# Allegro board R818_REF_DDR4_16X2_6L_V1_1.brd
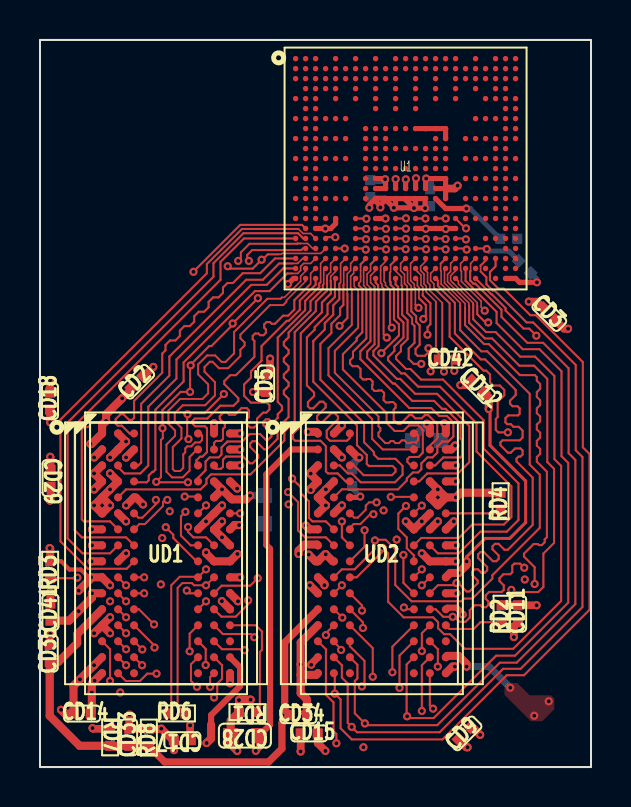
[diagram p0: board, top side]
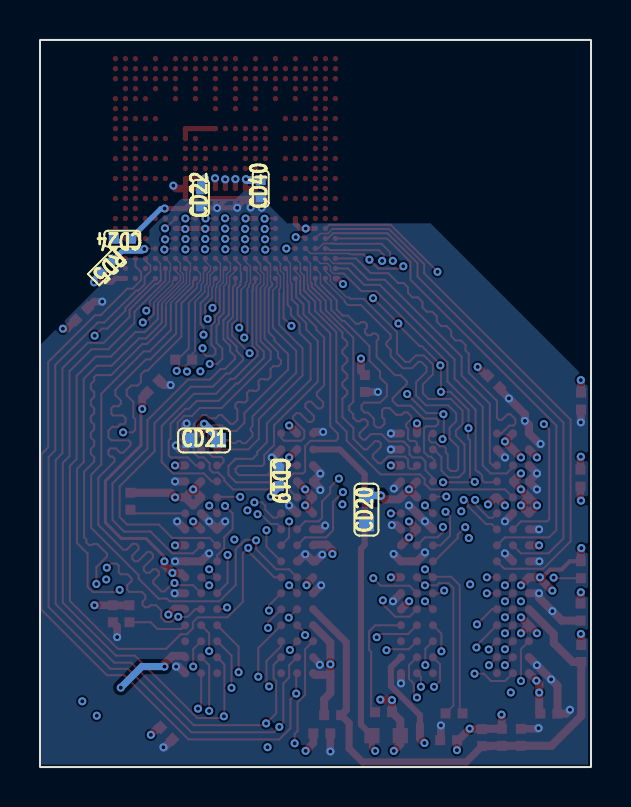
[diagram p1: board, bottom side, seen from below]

Outline 27.56 x 36.39 mm; copper layers: TOP, GND02, GND03, SIG04, GND05, BOTTOM. Coordinates in mm from the lower left corner of the outline.
Outline path: rectangle 0,0 27.56,36.39

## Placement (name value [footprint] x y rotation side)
CD2  1uF  [C0402]  4.86 19.29 45 top
CD3  1uF  [C0402]  25.47 22.67 315 top
CD5  100nF  [C0402]  11.31 19.2 90 top
CD9  NC/1uF  [C0402]  21.23 1.68 45 top
CD11  100nF  [C0402]  23.91 7.67 90 top
CD12  100nF  [C0402]  21.9 19.04 315 top
CD14  1uF  [C0402]  2.11 2.68 0 top
CD15  1uF  [C0402]  13.46 1.69 0 top
CD17  100nF  [C0402]  7.12 1.34 180 top
CD18  100nF  [C0402]  0.5 18.32 90 top
CD19  1uF  [C0402]  15.61 14.49 270 bottom
CD20  10uF  [C0603]  11.23 12.88 90 bottom
CD21  10uF  [C0603]  19.35 16.35 180 bottom
CD22  1uF  [C0402]  19.51 28.49 90 bottom
CD24  100nF  [C0402]  23.44 26.45 0 bottom
CD28  10uF  [C0603]  10.25 1.57 180 top
CD29  100nF  [C0402]  0.53 14.46 270 top
CD33  100nF  [C0402]  4.46 1.49 90 top
CD34  100nF  [C0402]  12.92 2.6 0 top
CD35  100nF  [C0402]  0.49 5.68 90 top
CD40  NC/1uF  [C0402]  16.52 28.95 90 bottom
CD41  NC/100nF  [C0402]  0.52 7.75 90 top
CD42  NC/2.2nF  [C0402]  20.37 20.39 0 top
NOREF  -  []  27.56 0 90 top
NOREF#2  -  []  0 36.39 0 top
NOREF#3  -  []  -29.69 -34.38 0 top
RD1  240R-1%  [R0402]  10.38 2.75 180 top
RD2  240R-1%  [R0402]  23.09 7.67 90 top
RD3  240R-1%  [R0402]  0.51 9.88 90 top
RD4  240R-1%  [R0402]  23.04 13.3 90 top
RD5  240R-1%  [R0402]  24.24 25.03 315 bottom
RD6  100R  [R0402]  6.85 2.68 0 top
RD7  2K-1%  [R0402]  3.51 1.49 270 top
RD8  2K-1%  [R0402]  5.45 1.47 90 top
U1  R818  [BGA346P50B1200_1200H114]  18.29 29.96 0 top
UD1  DDR4-FBGA96  [BGA96P80B1000_1400H120]  6.3 10.7 0 top
UD2  DDR4-FBGA96  [BGA96P80B1000_1400H120]  17.1 10.7 0 top

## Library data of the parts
CD2 CD3 CD5 CD9 CD11 CD12 CD14 CD15 CD17-CD22 CD24 CD29 CD33-CD35 CD40-CD42 = C-C0402-X5R
CD28 = C-C0603-X5R
RD1-RD5 RD7 RD8 = R-R0402-1%
RD6 = R-R0402-5%
U1 = A100-BGA
UD1 UD2 = DDR4-FBGA96

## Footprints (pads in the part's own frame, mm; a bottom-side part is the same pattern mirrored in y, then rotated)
BGA96P80B1000_1400H120
  round 0.4 smd: A1(-3.2,6) A2(-2.4,6) A3(-1.6,6) A7(1.6,6) A8(2.4,6) A9(3.2,6) B1(-3.2,5.2) B2(-2.4,5.2) B3(-1.6,5.2) B7(1.6,5.2) B8(2.4,5.2) B9(3.2,5.2) C1(-3.2,4.4) C2(-2.4,4.4) C3(-1.6,4.4) C7(1.6,4.4) C8(2.4,4.4) C9(3.2,4.4) D1(-3.2,3.6) D2(-2.4,3.6) D3(-1.6,3.6) D7(1.6,3.6) D8(2.4,3.6) D9(3.2,3.6) E1(-3.2,2.8) E2(-2.4,2.8) E3(-1.6,2.8) E7(1.6,2.8) E8(2.4,2.8) E9(3.2,2.8) F1(-3.2,2) F2(-2.4,2) F3(-1.6,2) F7(1.6,2) F8(2.4,2) F9(3.2,2) G1(-3.2,1.2) G2(-2.4,1.2) G3(-1.6,1.2) G7(1.6,1.2) G8(2.4,1.2) G9(3.2,1.2) H1(-3.2,0.4) H2(-2.4,0.4) H3(-1.6,0.4) H7(1.6,0.4) H8(2.4,0.4) H9(3.2,0.4) J1(-3.2,-0.4) J2(-2.4,-0.4) J3(-1.6,-0.4) J7(1.6,-0.4) J8(2.4,-0.4) J9(3.2,-0.4) K1(-3.2,-1.2) K2(-2.4,-1.2) K3(-1.6,-1.2) K7(1.6,-1.2) K8(2.4,-1.2) K9(3.2,-1.2) L1(-3.2,-2) L2(-2.4,-2) L3(-1.6,-2) L7(1.6,-2) L8(2.4,-2) L9(3.2,-2) M1(-3.2,-2.8) M2(-2.4,-2.8) M3(-1.6,-2.8) M7(1.6,-2.8) M8(2.4,-2.8) M9(3.2,-2.8) N1(-3.2,-3.6) N2(-2.4,-3.6) N3(-1.6,-3.6) N7(1.6,-3.6) N8(2.4,-3.6) N9(3.2,-3.6) P1(-3.2,-4.4) P2(-2.4,-4.4) P3(-1.6,-4.4) P7(1.6,-4.4) P8(2.4,-4.4) P9(3.2,-4.4) R1(-3.2,-5.2) R2(-2.4,-5.2) R3(-1.6,-5.2) R7(1.6,-5.2) R8(2.4,-5.2) R9(3.2,-5.2) T1(-3.2,-6) T2(-2.4,-6) T3(-1.6,-6) T7(1.6,-6) T8(2.4,-6) T9(3.2,-6)
BGA346P50B1200_1200H114
  round 0.27 smd: A1(-5.5,5.5) A2(-5,5.5) A3(-4.5,5.5) A5(-3.5,5.5) A7(-2.5,5.5) A9(-1.5,5.5) A11(-0.5,5.5) A12(0,5.5) A13(0.5,5.5) A14(1,5.5) A15(1.5,5.5) A16(2,5.5) A17(2.5,5.5) A19(3.5,5.5) A21(4.5,5.5) A22(5,5.5) A23(5.5,5.5) AA1(-5.5,-4.5) AA2(-5,-4.5) AA3(-4.5,-4.5) AA4(-4,-4.5) AA5(-3.5,-4.5) AA6(-3,-4.5) AA7(-2.5,-4.5) AA8(-2,-4.5) AA9(-1.5,-4.5) AA10(-1,-4.5) AA11(-0.5,-4.5) AA12(0,-4.5) AA13(0.5,-4.5) AA14(1,-4.5) AA15(1.5,-4.5) AA16(2,-4.5) AA17(2.5,-4.5) AA18(3,-4.5) AA19(3.5,-4.5) AA20(4,-4.5) AA21(4.5,-4.5) AA22(5,-4.5) AA23(5.5,-4.5) AB1(-5.5,-5) AB2(-5,-5) AB3(-4.5,-5) AB4(-4,-5) AB5(-3.5,-5) AB6(-3,-5) AB7(-2.5,-5) AB8(-2,-5) AB9(-1.5,-5) AB10(-1,-5) AB11(-0.5,-5) AB12(0,-5) AB13(0.5,-5) AB14(1,-5) AB15(1.5,-5) AB16(2,-5) AB17(2.5,-5) AB18(3,-5) AB19(3.5,-5) AB20(4,-5) AB22(5,-5) AB23(5.5,-5) AC1(-5.5,-5.5) AC2(-5,-5.5) AC3(-4.5,-5.5) AC5(-3.5,-5.5) AC7(-2.5,-5.5) AC9(-1.5,-5.5) AC11(-0.5,-5.5) AC13(0.5,-5.5) AC15(1.5,-5.5) AC17(2.5,-5.5) AC19(3.5,-5.5) AC21(4.5,-5.5) AC22(5,-5.5) AC23(5.5,-5.5) B1(-5.5,5) B2(-5,5) B3(-4.5,5) B4(-4,5) B5(-3.5,5) B6(-3,5) B7(-2.5,5) B8(-2,5) B9(-1.5,5) B10(-1,5) B11(-0.5,5) B12(0,5) B13(0.5,5) B14(1,5) B15(1.5,5) B16(2,5) B17(2.5,5) B18(3,5) B19(3.5,5) B20(4,5) B21(4.5,5) B22(5,5) B23(5.5,5) C1(-5.5,4.5) C2(-5,4.5) C3(-4.5,4.5) C4(-4,4.5) C5(-3.5,4.5) C6(-3,4.5) C7(-2.5,4.5) C8(-2,4.5) C9(-1.5,4.5) C10(-1,4.5) C11(-0.5,4.5) C13(0.5,4.5) C15(1.5,4.5) C17(2.5,4.5) C18(3,4.5) C19(3.5,4.5) C20(4,4.5) C21(4.5,4.5) C22(5,4.5) C23(5.5,4.5) D2(-5,4) D3(-4.5,4) D4(-4,4) D5(-3.5,4) D7(-2.5,4) D9(-1.5,4) D11(-0.5,4) D13(0.5,4) D15(1.5,4) D17(2.5,4) D19(3.5,4) D21(4.5,4) D22(5,4) E1(-5.5,3.5) E2(-5,3.5) E3(-4.5,3.5) E5(-3.5,3.5) E7(-2.5,3.5) E9(-1.5,3.5) E11(-0.5,3.5) E13(0.5,3.5) E15(1.5,3.5) E17(2.5,3.5) E20(4,3.5) E21(4.5,3.5) E22(5,3.5) E23(5.5,3.5) F2(-5,3) F3(-4.5,3) F9(-1.5,3) F11(-0.5,3) F13(0.5,3) F22(5,3) F23(5.5,3) G1(-5.5,2.5) G2(-5,2.5) G3(-4.5,2.5) G4(-4,2.5) G5(-3.5,2.5) G6(-3,2.5) G19(3.5,2.5) G20(4,2.5) G21(4.5,2.5) G22(5,2.5) G23(5.5,2.5) H2(-5,2) H3(-4.5,2) H8(-2,2) H9(-1.5,2) H10(-1,2) H11(-0.5,2) H12(0,2) H13(0.5,2) H14(1,2) H15(1.5,2) H16(2,2) H22(5,2) H23(5.5,2) J1(-5.5,1.5) J2(-5,1.5) J3(-4.5,1.5) J4(-4,1.5) J5(-3.5,1.5) J6(-3,1.5) J8(-2,1.5) J9(-1.5,1.5) J10(-1,1.5) J15(1.5,1.5) J16(2,1.5) J18(3,1.5) J19(3.5,1.5) J20(4,1.5) J21(4.5,1.5) J22(5,1.5) J23(5.5,1.5) K2(-5,1) K3(-4.5,1) K8(-2,1) K9(-1.5,1) K10(-1,1) K11(-0.5,1) K12(0,1) K13(0.5,1) K14(1,1) K15(1.5,1) K16(2,1) K21(4.5,1) K22(5,1) L1(-5.5,0.5) L2(-5,0.5) L3(-4.5,0.5) L4(-4,0.5) L5(-3.5,0.5) L6(-3,0.5) L8(-2,0.5) L9(-1.5,0.5) L10(-1,0.5) L14(1,0.5) L15(1.5,0.5) L16(2,0.5) L18(3,0.5) L19(3.5,0.5) L20(4,0.5) L21(4.5,0.5) L22(5,0.5) L23(5.5,0.5) M2(-5,0) M3(-4.5,0) M8(-2,0) M9(-1.5,0) M10(-1,0) M11(-0.5,0) M12(0,0) M13(0.5,0) M14(1,0) M15(1.5,0) M16(2,0) M21(4.5,0) M22(5,0) N1(-5.5,-0.5) N2(-5,-0.5) N3(-4.5,-0.5) N4(-4,-0.5) N5(-3.5,-0.5) N6(-3,-0.5) N8(-2,-0.5) N9(-1.5,-0.5) N15(1.5,-0.5) N16(2,-0.5) N18(3,-0.5) N19(3.5,-0.5) N20(4,-0.5) N21(4.5,-0.5) N22(5,-0.5) N23(5.5,-0.5) P2(-5,-1) P3(-4.5,-1) P8(-2,-1) P9(-1.5,-1) P10(-1,-1) P11(-0.5,-1) P12(0,-1) P13(0.5,-1) P14(1,-1) P15(1.5,-1) P16(2,-1) P21(4.5,-1) P22(5,-1) R1(-5.5,-1.5) R2(-5,-1.5) R3(-4.5,-1.5) R4(-4,-1.5) R5(-3.5,-1.5) R6(-3,-1.5) R8(-2,-1.5) R9(-1.5,-1.5) R10(-1,-1.5) R11(-0.5,-1.5) R12(0,-1.5) R13(0.5,-1.5) R14(1,-1.5) R15(1.5,-1.5) R16(2,-1.5) R18(3,-1.5) R19(3.5,-1.5) R20(4,-1.5) R21(4.5,-1.5) R22(5,-1.5) R23(5.5,-1.5) T2(-5,-2) T3(-4.5,-2) T21(4.5,-2) T22(5,-2) U1(-5.5,-2.5) U2(-5,-2.5) U3(-4.5,-2.5) U4(-4,-2.5) U5(-3.5,-2.5) U7(-2.5,-2.5) U9(-1.5,-2.5) U11(-0.5,-2.5) U13(0.5,-2.5) U15(1.5,-2.5) U17(2.5,-2.5) U18(3,-2.5) U19(3.5,-2.5) U20(4,-2.5) U21(4.5,-2.5) U22(5,-2.5) U23(5.5,-2.5) V2(-5,-3) V3(-4.5,-3) V7(-2.5,-3) V9(-1.5,-3) V11(-0.5,-3) V13(0.5,-3) V15(1.5,-3) V17(2.5,-3) V22(5,-3) V23(5.5,-3) W1(-5.5,-3.5) W2(-5,-3.5) W3(-4.5,-3.5) W4(-4,-3.5) W7(-2.5,-3.5) W9(-1.5,-3.5) W11(-0.5,-3.5) W13(0.5,-3.5) W15(1.5,-3.5) W17(2.5,-3.5) W20(4,-3.5) W21(4.5,-3.5) W22(5,-3.5) W23(5.5,-3.5) Y2(-5,-4) Y3(-4.5,-4) Y4(-4,-4) Y5(-3.5,-4) Y7(-2.5,-4) Y9(-1.5,-4) Y11(-0.5,-4) Y13(0.5,-4) Y15(1.5,-4) Y17(2.5,-4) Y19(3.5,-4) Y22(5,-4) Y23(5.5,-4)
C0402
  rect 0.5x0.5 smd: 1(-0.425,0) 2(0.425,0)
C0603
  rect 0.76x0.76 smd: 1(-0.71,0) 2(0.71,0)
R0402
  rect 0.5x0.5 smd: 1(-0.425,0) 2(0.425,0)

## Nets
GND: CD2.2 CD3.2 CD5.2 CD9.2 CD11.2 CD12.2 CD14.2 CD15.2 CD17.2 CD18.2 CD19.2 CD20.2 CD21.2 CD22.2 CD24.2 CD28.2 CD29.2 CD33.2 CD34.2 CD35.2 CD40.2 CD41.2 RD1.2 RD2.2 RD3.2 RD4.2 RD5.2 RD8.2 U1.A1(GND1) U1.A23(GND2) U1.AA7(GND58) U1.AA11(GND59) U1.AA13(GND60) U1.AA18(GND61) U1.AC1(GND62) U1.AC22(GND63) U1.AC23(GND64) U1.C17(GND3) U1.C19(GND4) U1.H8(GND5) U1.H9(GND6) U1.H10(GND7) U1.H11(GND8) U1.J3(GND9) U1.J8(GND10) U1.J9(GND11) U1.J10(GND12) U1.J15(GND13) U1.J21(GND14) U1.K10(GND15) U1.K11(GND16) U1.K12(GND17) U1.K13(GND18) U1.K14(GND19) U1.K15(GND20) U1.K16(GND21) U1.L9(GND22) U1.L10(GND23) U1.L14(GND24) U1.L15(GND25) U1.L16(GND26) U1.M9(GND27) U1.M10(GND28) U1.M11(GND29) U1.M12(GND30) U1.M13(GND31) U1.M14(GND32) U1.M15(GND33) U1.M16(GND34) U1.N9(GND35) U1.N15(GND36) U1.N16(GND37) U1.N22(GND38) U1.P9(GND39) U1.P10(GND40) U1.P11(GND41) U1.P12(GND42) U1.P13(GND43) U1.P14(GND44) U1.P15(GND45) U1.P16(GND46) U1.R8(GND47) U1.R16(GND48) U1.R21(GND49) U1.U5(GND50) U1.U9(GND51) U1.V2(GND52) U1.V3(GND53) U1.V13(GND54) U1.V15(GND55) U1.V17(GND56) U1.Y4(GND57) UD1.A2(VSSQ1) UD1.A8(VSSQ2) UD1.B2(VSS1) UD1.C9(VSSQ3) UD1.D2(VSSQ4) UD1.D8(VSSQ5) UD1.E1(VSS2) UD1.E3(VSSQ6) UD1.E8(VSSQ7) UD1.E9(VSS3) UD1.F1(VSSQ8) UD1.G8(VSS4) UD1.H1(VSSQ9) UD1.H9(VSSQ10) UD1.K1(VSS5) UD1.K9(VSS6) UD1.M9(VSS7) UD1.N1(VSS8) UD1.T1(VSS9) UD2.A2(VSSQ1) UD2.A8(VSSQ2) UD2.B2(VSS1) UD2.C9(VSSQ3) UD2.D2(VSSQ4) UD2.D8(VSSQ5) UD2.E1(VSS2) UD2.E3(VSSQ6) UD2.E8(VSSQ7) UD2.E9(VSS3) UD2.F1(VSSQ8) UD2.G8(VSS4) UD2.H1(VSSQ9) UD2.H9(VSSQ10) UD2.K1(VSS5) UD2.K9(VSS6) UD2.M9(VSS7) UD2.N1(VSS8) UD2.T1(VSS9)
VCC25-DRAM: CD28.1 CD29.1 UD1.B1(VPP1) UD1.R9(VPP2) UD2.B1(VPP1) UD2.R9(VPP2)
VCC-DRAM: CD2.1 CD3.1 CD5.1 CD9.1 CD11.1 CD12.1 CD14.1 CD15.1 CD17.1 CD18.1 CD19.1 CD20.1 CD21.1 CD22.1 CD40.1 CD41.1 RD7.1 U1.R9(VCC_DRAM1) U1.R10(VCC_DRAM2) U1.R11(VCC_DRAM3) U1.R12(VCC_DRAM4) U1.R13(VCC_DRAM5) U1.R14(VCC_DRAM6) UD1.A1(VDDQ1) UD1.A9(VDDQ2) UD1.B3(VDD1) UD1.B9(VDD2) UD1.C1(VDDQ3) UD1.D1(VDD3) UD1.D9(VDDQ4) UD1.F2(VDDQ5) UD1.F8(VDDQ6) UD1.G1(VDDQ7) UD1.G7(VDD4) UD1.G9(VDDQ8) UD1.J1(VDD5) UD1.J2(VDDQ9) UD1.J8(VDDQ10) UD1.J9(VDD6) UD1.L1(VDD7) UD1.L9(VDD8) UD1.R1(VDD9) UD1.T9(VDD10) UD2.A1(VDDQ1) UD2.A9(VDDQ2) UD2.B3(VDD1) UD2.B9(VDD2) UD2.C1(VDDQ3) UD2.D1(VDD3) UD2.D9(VDDQ4) UD2.F2(VDDQ5) UD2.F8(VDDQ6) UD2.G1(VDDQ7) UD2.G7(VDD4) UD2.G9(VDDQ8) UD2.J1(VDD5) UD2.J2(VDDQ9) UD2.J8(VDDQ10) UD2.J9(VDD6) UD2.L1(VDD7) UD2.L9(VDD8) UD2.R1(VDD9) UD2.T9(VDD10)
VDD18-DRAM: CD24.1 U1.R15(VDD18_DRAM)
VDD-CPU: U1.K8(VDD_CPU1) U1.K9(VDD_CPU2) U1.L8(VDD_CPU3) U1.M8(VDD_CPU4) U1.N8(VDD_CPU5)
VDD-SYS: U1.H13(VDD_SYS1) U1.H14(VDD_SYS2) U1.H15(VDD_SYS3) U1.H16(VDD_SYS4) U1.J16(VDD_SYS5)
SA0: U1.AC19(SA11) UD1.P3(A0) UD2.P3(A0)
SA1: U1.U15(SA3) UD1.P7(A1) UD2.P7(A1)
SA2: U1.AA19(SA9) UD1.R3(A2) UD2.R3(A2)
SA3: U1.Y15(SBA1) UD1.N7(A3) UD2.N7(A3)
SA4: U1.W15(SBA0) UD1.N3(A4) UD2.N3(A4)
SA5: U1.AB16(SA13) UD1.P8(A5) UD2.P8(A5)
SA6: U1.U13(SA4) UD1.P2(A6) UD2.P2(A6)
SA7: U1.W17(SA7) UD1.R8(A7) UD2.R8(A7)
SA8: U1.AA20(SACT) UD1.R2(A8) UD2.R2(A8)
SA9: U1.AB18(SA8) UD1.R7(A9) UD2.R7(A9)
SA10: U1.AB15(SA16) UD1.M3(A10) UD2.M3(A10)
SA11: U1.AA21(SODT0) UD1.T2(A11) UD2.T2(A11)
SA12: U1.AB12(SA15) UD1.M7(A12) UD2.M7(A12)
SA13: U1.Y17(SA12) UD1.T8(A13) UD2.T8(A13)
SACT: U1.AC13(SA14) UD1.L3(ACT) UD2.L3(ACT)
SBA0: U1.W13(SA5) UD1.N2(BA0) UD2.N2(BA0)
SBA1: U1.AA17(SA0) UD1.N8(BA1) UD2.N8(BA1)
SBG0: U1.Y13(SA6) UD1.M2(BG0) UD2.M2(BG0)
SCAS: U1.AC17(SA10) UD1.M8(A15/CAS) UD2.M8(A15/CAS)
SCKE0: U1.AA16(SCKE0) UD1.K2(CKE0) UD2.K2(CKE0)
SCKN: CD42.2 RD6.2 U1.AB14(SCKN) UD1.K8(CK#) UD2.K8(CK#)
SCKP: CD42.1 RD6.1 U1.AA14(SCKP) UD1.K7(CK) UD2.K7(CK)
SCS0: U1.AB13(SA1) UD1.L7(CS0) UD2.L7(CS0)
SDQ0: U1.Y7(SDQ0) UD1.F7(DQ1)
SDQ1: U1.V7(SDQ1) UD1.H8(DQ5)
SDQ2: U1.Y5(SDQ2) UD1.J7(DQ7)
SDQ3: U1.W7(SDQ3) UD1.H7(DQ3)
SDQ4: U1.W1(SDQ4) UD1.H3(DQ2)
SDQ5: U1.W4(SDQ5) UD1.G2(DQ0)
SDQ6: U1.W2(SDQ6) UD1.H2(DQ4)
SDQ7: U1.W3(SDQ7) UD1.J3(DQ6)
SDQ8: U1.AA1(SDQ8) UD1.A3(DQ8)
SDQ9: U1.AB4(SDQ9) UD1.C8(DQ13)
SDQ10: U1.AB1(SDQ10) UD1.C2(DQ12)
SDQ11: U1.AB3(SDQ11) UD1.C7(DQ11)
SDQ12: U1.AC3(SDQ12) UD1.B8(DQ9)
SDQ13: U1.AA4(SDQ13) UD1.D7(DQ15)
SDQ14: U1.AA3(SDQ14) UD1.D3(DQ14)
SDQ15: U1.AA2(SDQ15) UD1.C3(DQ10)
SDQ16: U1.AC9(SDQ16) UD2.D7(DQ15)
SDQ17: U1.AB9(SDQ17) UD2.C8(DQ13)
SDQ18: U1.AA8(SDQ18) UD2.C7(DQ11)
SDQ19: U1.AB8(SDQ19) UD2.B8(DQ9)
SDQ20: U1.AC5(SDQ20) UD2.A3(DQ8)
SDQ21: U1.AB5(SDQ21) UD2.D3(DQ14)
SDQ22: U1.AA6(SDQ22) UD2.C3(DQ10)
SDQ23: U1.AB6(SDQ23) UD2.C2(DQ12)
SDQ24: U1.Y11(SDQ24) UD2.J3(DQ6)
SDQ25: U1.W9(SDQ25) UD2.H2(DQ4)
SDQ26: U1.V9(SDQ26) UD2.H3(DQ2)
SDQ27: U1.Y9(SDQ27) UD2.G2(DQ0)
SDQ28: U1.AC11(SDQ28) UD2.H7(DQ3)
SDQ29: U1.W11(SDQ29) UD2.J7(DQ7)
SDQ30: U1.AB11(SDQ30) UD2.H8(DQ5)
SDQ31: U1.V11(SDQ31) UD2.F7(DQ1)
SDQM0: U1.U7(SDQM0) UD1.E7(DM0)
SDQM1: U1.AA5(SDQM1) UD1.E2(DM1)
SDQM2: U1.AA9(SDQM2) UD2.E2(DM1)
SDQM3: U1.U11(SDQM3) UD2.E7(DM0)
SDQS0N: U1.Y3(SDQS0N) UD1.F3(DQS0#)
SDQS0P: U1.Y2(SDQS0P) UD1.G3(DQS0)
SDQS1N: U1.AC2(SDQS1N) UD1.A7(DQS1#)
SDQS1P: U1.AB2(SDQS1P) UD1.B7(DQS1)
SDQS2N: U1.AC7(SDQS2N) UD2.A7(DQS1#)
SDQS2P: U1.AB7(SDQS2P) UD2.B7(DQS1)
SDQS3N: U1.AA10(SDQS3N) UD2.F3(DQS0#)
SDQS3P: U1.AB10(SDQS3P) UD2.G3(DQS0)
SODT0: U1.AB17(SBG0) UD1.K3(ODT0) UD2.K3(ODT0)
SRAS: U1.AC15(SCS0) UD1.L8(A16/RAS) UD2.L8(A16/RAS)
SRST: U1.U17(SRST) UD1.P1(RESET) UD2.P1(RESET)
STEN1: RD1.1 UD1.N9(TEN)
STEN2: RD2.1 UD2.N9(TEN)
SVREF: CD33.1 CD34.1 CD35.1 RD7.2 RD8.1 UD1.M1(VREFCA) UD2.M1(VREFCA)
SWE: U1.AA12(SA2) UD1.L2(A14/WE) UD2.L2(A14/WE)
N16281101: RD5.1 U1.Y19(SZQ)
N17928021: RD3.1 UD1.F9(ZQ)
N17931224: RD4.1 UD2.F9(ZQ)

Pads without a net: U1 A2 A3 A5 A7 A9 A11 A12 A13 A14 A15 A16 A17 A19 A21 A22 AA15 AA22 AA23 AB19 AB20 AB22 AB23 AC21 B1 B2 B3 B4 B5 B6 B7 B8 B9 B10 B11 B12 B13 B14 B15 B16 B17 B18 B19 B20 B21 B22 B23 C1 C2 C3 C4 C5 C6 C7 C8 C9 C10 C11 C13 C15 C18 C20 C21 C22 C23 D2 D3 D4 D5 D7 D9 D11 D13 D15 D17 D19 D21 D22 E1 E2 E3 E5 E7 E9 E11 E13 E15 E17 E20 E21 E22 E23 F2 F3 F9 F11 F13 F22 F23 G1 G2 G3 G4 G5 G6 G19 G20 G21 G22 G23 H2 H3 H12 H22 H23 J1 J2 J4 J5 J6 J18 J19 J20 J22 J23 K2 K3 K21 K22 L1 L2 L3 L4 L5 L6 L18 L19 L20 L21 L22 L23 M2 M3 M21 M22 N1 N2 N3 N4 N5 N6 N18 N19 N20 N21 N23 P2 P3 P8 P21 P22 R1 R2 R3 R4 R5 R6 R18 R19 R20 R22 R23 T2 T3 T21 T22 U1 U2 U3 U4 U18 U19 U20 U21 U22 U23 V22 V23 W20 W21 W22 W23 Y22 Y23; UD1 P9 T3 T7; UD2 P9 T3 T7

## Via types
v1: diameter 0.406, hole 0.203, TOP to BOTTOM, 280 vias

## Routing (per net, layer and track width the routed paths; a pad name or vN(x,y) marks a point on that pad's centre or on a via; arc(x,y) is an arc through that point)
GND: length 134.9
  TOP w0.076: U1.Y4 14.04,25.71 12.1,25.71 12.06,25.66 11.94,25.66 ; U1.AA18 21.04,25.21 21.04,24.85 21.08,24.81 21.08,24.31 22.06,23.32 22.06,23.02 v1(22.24,22.84) ; 17.5,24.75 17.54,24.78 17.54,25.14 ; U1.AA7 15.54,25.21 15.54,24.85 15.37,24.68 15.37,23.7 15.38,23.69 ; 18.77,23.14 18.77,23.97 18.72,24.02 18.72,24.17 18.53,24.35 18.53,25.21 U1.AA13
  TOP w0.102: 17.54,25.14 17.79,25.39 U1.AA11 ; v1(17.08,20.72) 17.08,20.73 17.95,21.6 17.95,22.16 17.7,22.41 17.7,23.97 17.54,24.14 17.54,24.27 17.5,24.31 17.5,24.75 ; 7.4,14.25 5.84,14.25 v1(5.81,14.28) 6.05,14.51 6.05,16.37 6.14,16.46 6.14,16.94 v1(6.13,16.96) 6.13,17.87 7.03,18.78 v1(7.51,18.78) 7.51,20.07 v1(7.54,20.1) 7.54,20.15 8.46,21.07 8.57,21.07 9.63,22.13 v1(9.63,22.2) v1(10.9,23.47) ; 18.77,23.14 v1(18.93,22.98) ; v1(7.68,24.79) 7.68,24.8 10.02,27.14 13.11,27.14 U1.V2 ; v1(9.39,25.07) 9.51,24.95 10.64,24.95 v1(11.08,25.39) 11.12,25.39 11.39,25.66 11.94,25.66 ; v1(7.43,16.41) 7.36,16.48 7.36,17.64 v1(7.38,17.66) 7.43,17.71 8.23,17.71 v1(9.19,18.67) ; v1(14.98,22.08) 15.38,22.48 15.38,23.69
  TOP w0.152: v1(22.44,17.92) 22.51,17.86 22.51,16.1 24.29,14.32 24.29,12.24 23.49,11.44 22.26,11.44 21.34,10.52 v1(21.34,10.3)
  TOP w0.203: RD3.2 1.06,10.3 1.47,9.89 2.04,9.89 2.43,9.5 v1(2.56,9.5)
  TOP w0.254: U1.P14 19.29,29.43 v1(19.31,29.46) 19.32,29.46 U1.N15 U1.N16 U1.P16 ; UD2.E3 15.98,13.5 v1(16.02,13.54) ; U1.P11 17.79,29.43 v1(17.79,29.43) ; U1.P16 U1.R16 ; U1.P16 U1.P15 ; U1.P12 18.29,29.41 v1(18.3,29.42) ; U1.P9 U1.P10 17.29,29.4 v1(17.26,29.42) 17.23,29.46 U1.N9 ; U1.V13 19.28,26.96 v1(19.3,26.94) 19.31,26.96 U1.V15 20.27,26.96 v1(20.29,26.93) 20.32,26.96 U1.V17 ; U1.AC1 12.68,24.46 v1(12.4,24.18) ; U1.AC22 U1.AC23 23.98,24.26 v1(24.85,24.26) ; v1(18.81,29.47) 18.79,29.45 U1.P13 ; U1.U9 v1(17.28,27.46) ; U1.V3 14.27,26.96 v1(14.27,26.95) 14.54,26.95 14.79,27.2 U1.U5
  TOP w0.305: UD2.M9 20.38,7.98 20.83,7.98 21.14,7.67 v1(21.14,7.63)
  TOP w0.381: v1(0.5,13.33) 0.53,13.36 CD29.2 ; RD8.2 6.04,1.9 v1(6.07,1.92) 6.64,1.34 CD17.2 6.69,0.86 v1(6.71,0.85) ; CD3.2 26.21,21.94 v1(26.41,21.94) ; v1(24.84,8.1) 24.83,8.1 CD11.2 RD2.2 ; CD5.2 11.51,19.82 v1(11.51,20.44) ; U1.P16 20.74,28.96 v1(20.89,29.1) ; v1(5.67,20.03) 5.23,19.59 CD2.2 ; CD33.2 4.46,2.61 v1(4.48,2.62) ; v1(14.27,0.81) 13.89,1.19 CD15.2 ; UD1.A2 v1(4.3,16.3) ; v1(5.15,13.14) 4.8,13.5 UD1.E3
  TOP w0.4: v1(9.95,3.35) 9.95,3.35 RD1.2 9.54,2.33 CD28.2 9.54,1.13 v1(9.86,0.81) ; UD1.N1 v1(3.5,7.5) ; UD1.N1 v1(3.5,6.7) ; UD1.N1 v1(2.7,6.7) ; UD2.K1 14.23,9.17 v1(14.23,9.1) ; UD1.E1 v1(2.7,13.1) UD1.F1 v1(3.5,13.1) UD1.E1 ; UD1.E1 v1(3.5,13.9) UD1.D2 v1(3.5,14.7) ; v1(21.34,10.3) 21.34,10.12 v1(20.94,9.72) 20.52,9.72 UD2.K9 ; v1(22.44,17.92) 22.44,18.5 CD12.2 ; UD2.D8 v1(19.9,13.9) ; v1(19.9,13.9) UD2.E9 ; v1(19.9,13.9) UD2.E8 19.9,13.1 UD2.E9 ; UD2.G8 v1(19.9,12.3) ; UD2.A2 v1(15.1,17.1) ; CD9.2 21.64,1.98 v1(22.01,1.61) ; UD1.H9 v1(9.1,11.5) UD1.G8 v1(9.1,12.3) ; UD2.D2 v1(14.3,13.9) UD2.E1 v1(14.3,13.1) UD2.F1 ; CD18.2 0.5,19.36 v1(0.51,19.37) ; UD2.N1 13.04,6.24 v1(13.04,5.14) ; UD1.E8 v1(9.1,13.9) ; v1(9.1,13.9) UD1.D8 ; v1(9.1,13.9) UD1.E9 9.6,13.4 10.32,13.4 v1(10.51,13.59) ; UD1.E3 v1(4.3,13.1) ; UD1.T1 v1(2.73,4.32) ; v1(0.51,8.75) 0.52,8.74 CD41.2 ; UD2.E9 v1(20.8,13.5) ; RD8.2 5.43,1.91 CD33.2 ; UD1.M9 v1(9.1,8.3) ; UD2.T1 13.82,4.61 13.04,4.61 13.04,4.61 ; CD35.2 0.49,6.64 v1(0.51,6.66) ; v1(3.5,9.1) UD1.K1 v1(2.56,9.5) ; UD1.H1 v1(2.6,11.1) ; v1(2.59,3.73) 2.59,2.73 CD14.2 ; UD2.A8 19.5,17.03 v1(19.35,17.18) ; v1(10.01,15.1) UD1.C9 ; v1(8.71,17.2) 8.7,17.2 UD1.A8 ; v1(3.5,15.5) UD1.B2 v1(4.3,16.3) ; UD2.H1 13.86,11.14 13.23,11.14 12.93,10.84 v1(12.93,10.67) ; UD1.K9 10.01,9.5 v1(10.01,9.5) ; UD2.H9 v1(20.8,11.1) ; UD2.B2 v1(15.1,15.5) ; CD34.2 13.35,3.39 ; UD2.C9 v1(20.8,15.1)
  TOP w0.406: v1(10.54,3.37) 9.98,3.37 v1(9.95,3.35) ; RD4.2 21.04,13.73 v1(20.8,13.5) ; v1(13.04,5.14) 13.04,3.7 13.35,3.39 ; v1(2.73,4.32) 2.59,4.18 v1(2.59,3.73) ; v1(0.48,10.96) 0.51,10.94 RD3.2 ; v1(1.94,8.83) 2.56,9.45 v1(2.56,9.5)
  SIG04 w0.102: v1(9.39,25.07) 9.53,25.21 9.53,25.45 9.8,25.72 10.75,25.72 v1(11.08,25.39)
  BOTTOM w0.254: v1(24.85,24.26) 24.85,24.42 RD5.2 ; v1(16.02,13.54) 15.61,13.94 CD19.2
  BOTTOM w0.381: CD22.2 19.51,29.26 v1(19.31,29.46) ; CD20.2 10.52,13.59 v1(10.51,13.59) ; v1(17.26,29.42) 17.21,29.38 CD40.2
  BOTTOM w0.406: v1(19.35,17.18) 18.64,16.47 CD21.2
  vias: v1(3.5,8.3) v1(4.01,3.73) v1(6.11,11.46) v1(6.05,9.14) v1(6.49,12.8) v1(7.4,14.25) v1(12.43,13.15) v1(16.18,0.99) v1(17.18,12.85) v1(17.84,11.39) v1(19.54,19.81) v1(24.25,9.39)
VCC25-DRAM: length 72.1
  TOP w0.305: UD1.R9 10.01,4.99 10.01,4.05 8.56,2.6 8.56,2.13 ; UD2.B1 12.57,15.9 11.32,14.65 11.32,11.11 11.51,10.93 11.51,2.12 CD28.1 10.96,0.97 v1(10.79,0.81)
  TOP w0.381: CD29.1 0.53,15.51 v1(0.51,15.53)
  TOP w0.4: v1(2.7,15.5) UD1.B1 ; v1(21.33,5.03) 21.33,5.16 20.93,5.56 20.37,5.56 UD2.R9 ; 8.56,1.43 8.56,2.13
  TOP w0.406: v1(8.33,1.2) 8.56,1.43
  SIG04 w0.406: 8.33,0.22 8.33,0.23 v1(8.33,1.2) ; 10.79,0.22 10.79,0.23 v1(10.79,0.81)
  SIG04 w0.508: 1.31,14.73 1.31,15.46 1.35,15.5 ; 1.31,14.73 0.54,15.5 ; 1.31,14.73 1.31,3.4 1.61,3.1 1.61,1.79 3.18,0.22 22.69,0.22 25.48,3.01 ; 0.54,15.5 v1(0.51,15.53) ; 0.54,15.5 1.35,15.5 ; 1.35,15.5 v1(2.7,15.5)
  BOTTOM w0.356: v1(21.33,5.03) 22.46,5.03 v1(23.52,3.97)
  vias: v1(24.72,2.57) v1(25.44,3.29)
VCC-DRAM: length 51.9
  TOP w0.254: U1.R9 16.8,28.47 17.27,28.47 U1.R10 ; U1.R9 16.79,28.33 17.02,28.09 ; U1.R9 16.47,28.14 v1(16.47,28) ; 17.02,28.09 v1(17.02,28.01) ; 17.02,28.09 17.02,28.13 17.29,28.39 17.29,28.4 ; U1.R10 17.29,28.4 ; U1.R10 U1.R11 ; U1.R12 U1.R11 ; U1.R12 U1.R13 ; U1.R12 18.29,28.4 18.69,27.99 v1(17.7,27.99) ; U1.R11 17.79,28.08 v1(17.7,27.99) ; U1.R13 18.79,28.06 v1(18.7,27.98) 19.26,27.98 v1(19.26,27.98) 19.26,28.43 U1.R14 U1.R13 ; v1(17.7,27.99) 17.29,28.4
  TOP w0.356: UD2.R1 13.56,5.16 v1(13.56,5.12)
  TOP w0.381: CD15.1 13.04,0.78 13.03,0.78 v1(13.03,0.78) ; v1(2.63,1.95) 2.66,1.91 RD7.1 ; v1(24.45,23.3) 24.85,23.3 CD3.1 ; CD17.1 7.51,1.38 v1(7.51,2.08) ; v1(4.11,18.45) 4.56,18.91 CD2.1 ; v1(23.7,6.5) 23.7,7.03 CD11.1 ; CD5.1 v1(10.66,18.77)
  TOP w0.4: UD2.G1 13.49,11.9 v1(13.29,12.09) ; UD1.D9 v1(9.86,13.94) ; v1(13.54,13.87) 13.54,13.94 UD2.D1 13.54,14.65 v1(13.54,14.69) 13.54,14.74 UD2.C1 ; v1(20.75,5.03) 20.63,5.03 UD2.T9 ; UD2.G9 v1(20.7,12.3) ; CD12.1 21.37,19.12 v1(21.03,19.12) ; UD2.A1 13.82,16.78 v1(13.4,16.78) ; UD1.J1 v1(2.58,10.3) ; UD1.G1 v1(2.6,11.9) ; CD18.1 0.51,17.88 v1(0.51,17.25) ; v1(8.31,10.74) 8.31,10.69 UD1.J8 UD1.J9 v1(9.87,10.67) ; v1(2.6,8.7) UD1.L1 ; 1.62,2.68 CD14.1 ; 1.62,2.68 1.68,2.73 1.68,4.07 ; 1.62,2.68 1.24,2.68 v1(1.05,2.87) ; UD1.L9 v1(9.9,8.3) ; v1(18.3,12.3) UD2.G7 v1(19.1,12.3) UD2.F8 ; v1(19.1,10.7) UD2.J8 UD2.J9 v1(20.8,10.3) ; v1(2.7,13.9) UD1.D1 v1(2.7,14.7) UD1.C1 ; v1(21.38,0.99) 21.32,0.99 CD9.1 ; v1(9.5,4.19) UD1.T9 ; v1(9.1,13.1) UD1.F8 v1(8.3,12.3) UD1.G7 ; v1(2.52,16.17) 2.58,16.17 UD1.A1 ; UD2.F2 v1(15.1,13.1) ; v1(13.44,10.63) 13.78,10.3 UD2.J1 14.25,10.65 v1(14.29,10.65) 14.65,10.3 UD2.J2 ; UD2.L1 v1(13.5,9.1) ; v1(20.82,8.7) UD2.L9 ; UD2.A9 20.3,17.12 v1(20.22,17.2) ; v1(4.3,10.7) UD1.J2 ; v1(4.3,15.5) UD1.B3 ; UD2.D9 v1(20.8,14.3) ; UD2.B9 20.57,15.9 v1(20.76,16.09) ; v1(15.97,15.49) 15.9,15.49 UD2.B3 ; CD41.1 1.45,7.33 1.47,7.34 ; UD1.R1 v1(2.7,5.1) ; v1(9.96,12.11) 9.72,12.11 UD1.G9 ; UD1.A9 v1(10.01,16.7) ; UD1.F2 v1(4.3,12.3) ; v1(10.01,15.9) UD1.B9
  TOP w0.406: 1.47,7.34 v1(1.93,7.8) 2.6,8.47 v1(2.6,8.7) ; v1(2.7,5.1) v1(2,4.39) 1.68,4.07 ; 4.09,18.44 3.3,17.65 v1(3.3,17.33) 3.1,17.13 UD1.A1
  BOTTOM w0.381: v1(15.97,15.49) 15.61,15.14 CD19.1
VDD18-DRAM: length 4.1
  TOP w0.254: U1.R15 20.29,27.96 v1(21.32,27.96)
  BOTTOM w0.254: v1(21.32,27.96) 21.51,27.96 CD24.1
VDD-SYS: length 2
  TOP w0.254: U1.J16 U1.H16 U1.H15 U1.H14 U1.H13
SA0: length 47.1
  TOP w0.102: v1(24.82,21.59) 24.47,21.95 24.19,21.95 23.28,22.85 23.28,22.97 22.59,23.67 22.57,23.67 U1.AC19 ; v1(16.1,4.03) 16.13,4.03 16.23,4.13 16.23,5.31 15.5,6.04 UD2.P3 ; UD1.P3 v1(5.12,5.89)
  SIG04 w0.114: v1(5.12,5.89) 5.19,5.89 6.35,4.73 9.48,4.73 10.13,4.08 11.34,4.08 11.72,3.7 14.24,3.7 14.58,4.04 14.89,4.04 14.9,4.03 v1(16.1,4.03) 16.57,3.57 19.51,3.57 19.83,3.25 22.07,3.25 22.43,3.61 22.64,3.61 23.39,4.36 24.05,4.36 26.36,6.67 26.36,19.64 24.82,21.18 v1(24.82,21.59)
SA1: length 47.9
  TOP w0.102: v1(8.29,5.11) 8.29,5.91 UD1.P7 ; U1.U15 v1(20.29,27.46) ; v1(17.98,3.96) 17.98,5.58 UD2.P7
  SIG04 w0.114: v1(8.29,5.11) 9.55,5.11 10.22,4.44 12.15,4.44 12.54,4.05 14.05,4.05 14.39,4.4 16.26,4.4 16.69,3.96 v1(17.98,3.96) 17.98,3.96 19.57,3.96 19.93,3.61 21.92,3.61 22.28,3.96 22.5,3.96 23.22,4.68 23.87,4.68 26.01,6.82 26.01,19.49 24.44,21.06 24.44,21.76 23.27,22.93 23.27,23.44 22.74,23.97 22.06,23.97 20.98,25.06 20.96,25.06 20.94,25.08 20.94,26.26 20.94,26.26 20.94,26.56 20.94,26.56 20.94,26.81 v1(20.29,27.46)
SA2: length 50.5
  TOP w0.076: 21.54,24.83 21.54,25.21 U1.AA19
  TOP w0.102: UD1.R3 4.71,5.5 v1(5.1,5.1) ; UD2.R3 15.87,5.12 15.87,4.44 15.75,4.31 15.75,2.69 v1(16.25,2.18) 16.34,2.1 19.87,2.1 23,5.22 23.84,5.22 26.78,8.16 26.78,15.37 26.44,15.71 26.44,19.96 25.16,21.24 24.37,21.24 23.08,22.53 23.08,22.89 21.78,24.19 21.68,24.19 21.52,24.35 21.52,24.35 21.52,24.36 21.52,24.81 21.54,24.83
  SIG04 w0.114: v1(5.1,5.1) 5.1,4.77 5.86,4.02 7.16,4.02 9.28,1.9 14.92,1.9 14.98,1.96 15.46,2.44 15.69,2.44 15.89,2.23 16.2,2.23 v1(16.25,2.18)
SA3: length 45.9
  TOP w0.102: v1(7.48,5.79) 7.48,6.68 UD1.N7 ; v1(20.29,25.91) 20.24,25.96 U1.Y15 ; UD2.N7 17.63,6.02 v1(17.63,4.74)
  SIG04 w0.114: v1(7.48,5.79) 7.49,5.8 9.76,5.8 10.41,5.15 12.45,5.15 12.84,4.76 13.71,4.76 14.11,5.15 16.52,5.15 16.93,4.74 v1(17.63,4.74) 17.7,4.67 19.78,4.67 20.13,4.32 21.63,4.32 21.98,4.67 22.21,4.67 22.99,5.46 23.64,5.46 25.3,7.11 25.3,19.19 23.76,20.73 23.76,21.46 22.6,22.61 22.6,23.04 22.38,23.26 21.84,23.26 20.42,24.68 20.42,24.89 20.29,25.02 v1(20.29,25.91)
SA4: length 49.4
  TOP w0.102: v1(16.64,4.52) 16.64,5.95 15.97,6.62 UD2.N3 ; U1.W15 20.25,26.46 v1(20.28,26.43) ; v1(5.73,5.98) 5.73,6.07 UD1.N3
  SIG04 w0.114: 16.67,4.52 v1(16.64,4.52) ; 16.67,4.52 16.86,4.32 19.66,4.32 20.02,3.96 21.77,3.96 22.13,4.32 22.36,4.32 23.08,5.04 23.73,5.04 25.65,6.97 25.65,19.34 24.11,20.88 24.11,21.61 22.95,22.77 22.95,23.14 22.48,23.62 21.97,23.62 20.65,24.93 20.65,26.06 20.29,26.43 v1(20.28,26.43) ; 16.67,4.52 16.67,4.53 16.49,4.71 14.16,4.71 13.86,4.41 12.69,4.41 12.26,4.83 10.27,4.83 9.64,5.47 7.67,5.47 7.63,5.43 6.28,5.43 v1(5.73,5.98)
SA5: length 41.5
  TOP w0.076: 21.26,23 21.26,23.2 20.23,24.23 20.23,24.9 U1.AB16
  TOP w0.102: UD1.P8 9.1,5.9 10.18,5.9 v1(10.23,5.85) ; 21.26,23 21.26,22.12 22.21,21.17 22.45,21.17 24,19.62 24.75,19.62 24.85,19.52 24.85,19.34 25.02,19.17 25.02,18.93 24.85,18.77 24.85,18.53 25.02,18.36 25.02,18.12 24.85,17.95 24.85,17.71 25.02,17.55 25.02,17.31 24.85,17.14 24.85,16.9 25.02,16.73 25.02,16.5 24.85,16.33 24.85,16.09 25.02,15.92 25.02,15.68 24.85,15.51 24.85,15.29 25.35,14.78 25.35,11.51 25.24,11.39 25.24,11.25 25.1,11.11 24.95,11.11 24.9,11.16 24.69,11.16 24.21,10.68 24.21,10.54 24.74,10 v1(24.74,9.16) ; v1(19.9,5.03) 19.9,5.03 19.9,5.9 UD2.P8
  SIG04 w0.114: v1(10.23,5.85) 10.57,5.51 14.9,5.51 14.91,5.5 16.65,5.5 17.01,5.13 17.93,5.13 18.03,5.03 v1(19.9,5.03) 20.06,5.03 20.44,4.65 21.47,4.65 21.85,5.03 22.06,5.03 22.86,5.83 23.56,5.83 24.47,6.74 24.47,8.89 v1(24.74,9.16)
SA6: length 45.3
  TOP w0.102: v1(15.06,5.86) 15.06,5.91 14.7,6.27 UD2.P2 ; U1.U13 v1(19.28,27.46) ; v1(4.3,5.9) UD1.P2
  SIG04 w0.114: v1(4.3,5.9) 4.78,6.37 7.28,6.37 7.46,6.2 10,6.2 10.11,6.31 10.33,6.31 10.77,5.86 v1(15.06,5.86) 16.79,5.86 17.16,5.49 18.45,5.49 18.52,5.41 21.94,5.41 23.42,6.89 23.6,6.89 23.62,6.9 24.11,7.4 24.11,8.84 23.82,9.13 23.82,10.23 24.11,10.52 24.11,19.15 22.97,20.29 22.97,20.97 21.86,22.08 21.86,22.78 20.07,24.57 20.07,24.89 19.92,25.04 19.92,26.93 19.39,27.46 v1(19.28,27.46)
SA7: length 49.7
  TOP w0.102: UD2.R8 19.1,5.1 v1(19.1,2.81) ; UD1.R8 9.1,5.1 9.1,4.41 8.86,4.17 8.86,3.64 v1(8.71,3.48) ; v1(21.3,26.41) 21.26,26.46 U1.W17
  SIG04 w0.114: v1(8.71,3.48) 9.56,2.63 14.7,2.63 15.3,3.23 15.9,3.23 16.23,2.9 19,2.9 v1(19.1,2.81) 19.39,2.52 22.34,2.52 22.72,2.9 23.53,2.9 27.08,6.44 27.08,19.96 25.5,21.53 25.5,21.92 25.15,22.27 24.9,22.27 23.95,23.22 23.95,23.91 23.17,24.68 22.32,24.68 21.71,25.29 21.71,25.48 21.71,25.49 21.71,26.19 21.49,26.41 v1(21.3,26.41)
SA8: length 51.7
  TOP w0.076: 22.04,24.81 22.04,25.08 22.03,25.08 22.03,25.1
  TOP w0.102: U1.AA20 22.29,25.35 22.03,25.1 ; 22.04,24.81 22.33,24.52 22.33,24.17 22.64,23.85 22.74,23.85 24.34,22.25 24.67,22.25 26.79,20.12 26.79,15.85 27.13,15.52 27.13,8.01 24.04,4.92 23.16,4.92 19.98,1.74 15.86,1.74 v1(15.59,2.01) 15.39,2.21 15.39,4.18 15.1,4.47 15.1,5.1 UD2.R2 ; v1(4.3,5.1) UD1.R2
  SIG04 w0.114: v1(15.59,2.01) 15.15,1.57 9.11,1.57 7.02,3.66 5.44,3.66 4.3,4.8 v1(4.3,5.1)
SA9: length 46.4
  TOP w0.102: UD2.R7 18.34,5.14 18.34,2.56 v1(18.36,2.54) 18.45,2.45 19.69,2.45 22.81,5.57 23.76,5.57 26.42,8.23 26.42,15.22 26.08,15.56 26.08,19.81 24.98,20.91 24.14,20.91 22.84,22.22 22.84,22.78 21.29,24.33 U1.AB18 ; v1(7.85,4.02) 7.55,4.31 7.55,5.14 UD1.R7
  SIG04 w0.114: v1(18.36,2.54) 18.32,2.58 16.09,2.58 16.04,2.59 15.75,2.87 15.45,2.87 14.85,2.27 9.36,2.27 7.85,3.79 v1(7.85,4.02)
SA10: length 40.8
  TOP w0.076: 19.79,23.9 19.7,23.99 19.7,24.18 19.54,24.35 19.54,24.71 U1.AB15
  TOP w0.102: v1(16.15,6.96) 16.15,7.24 UD2.M3 ; 19.79,23.9 20.49,23.21 20.49,21.54 22.18,19.84 22.32,19.84 22.51,19.65 22.51,19.26 22.67,19.1 23,19.1 23.22,18.87 23.22,18.61 22.89,18.28 22.89,17.51 22.8,17.42 22.8,16.88 22.92,16.75 v1(23.4,16.75) ; v1(5.7,7.14) 4.95,7.9 UD1.M3
  SIG04 w0.114: v1(5.7,7.14) 7.52,7.14 7.8,6.86 9.67,6.86 9.99,7.18 11.87,7.18 12.08,6.97 14.45,6.97 14.46,6.96 v1(16.15,6.96) 17.2,6.96 17.6,6.55 19.46,6.55 19.56,6.45 21.47,6.45 22.79,7.77 22.79,9.09 23.15,9.45 23.15,10.56 23.4,10.81 v1(23.4,16.75)
SA11: length 50.2
  TOP w0.102: U1.AA21 22.79,25.06 22.5,24.78 22.5,24.37 22.93,23.94 23.19,23.94 24.52,22.62 24.81,22.62 27.15,20.27 27.15,16 27.49,15.67 27.49,7.87 24.21,4.59 23.34,4.59 20.13,1.38 15.59,1.38 15.03,1.94 15.03,3.39 v1(14.74,3.68) 14.74,3.68 14.74,4.65 UD2.T2 ; v1(5.83,4.67) 5.36,4.67 5,4.31 4.29,4.31 UD1.T2
  SIG04 w0.114: v1(5.83,4.67) 6.1,4.4 8.78,4.4 9.45,3.73 11.18,3.73 11.58,3.34 14.41,3.34 v1(14.74,3.68)
SA12: length 40
  TOP w0.076: 18.57,23.95 18.57,24.07 18.38,24.26 18.38,24.86 U1.AB12
  TOP w0.102: UD2.M7 18.29,7.9 v1(18.2,7.98) ; UD1.M7 v1(8.3,8.3) ; 18.57,23.95 18.57,22.81 18.82,22.57 18.82,22.28 18.99,22.11 18.99,21.13 18.78,20.93 18.78,20.69 18.88,20.58 19.25,20.58 19.43,20.76 v1(19.43,20.96)
  SIG04 w0.102: 19.43,20.97 v1(19.43,20.96)
  SIG04 w0.114: v1(19.43,20.96) 19.69,20.7 20.19,20.7 20.32,20.83 20.32,20.99 20.2,21.12 19.97,21.12 19.87,21.22 19.87,21.42 19.98,21.53 20.45,21.53 21.56,20.43 21.56,19.61 21.75,19.41 21.75,19.05 21.79,19 22.16,19 22.29,18.87 22.29,18.62 22.18,18.51 21.56,18.51 21.44,18.4 21.44,18.16 21.78,17.82 22.01,17.82 22.18,17.66 22.18,17.41 22.36,17.23 22.36,11.48 22.23,11.36 22.04,11.36 21.79,11.11 21.79,10.85 22.08,10.56 22.08,9.89 21.68,9.49 21.68,8.12 21.55,7.98 21.3,7.98 21.29,7.99 20.99,7.99 20.98,7.98 v1(18.2,7.98) 17.65,8.54 14.69,8.54 14.54,8.39 12.79,8.39 12.47,8.71 9.8,8.71 9.54,8.45 9.54,8.24 9.25,7.94 8.66,7.94 v1(8.3,8.3)
SA13: length 46.1
  TOP w0.102: v1(21.34,25.9) 21.28,25.96 U1.Y17 ; v1(8.51,4.02) 8.51,4.5 UD1.T8 ; UD2.T8 19.5,3.08 v1(19.66,2.92)
  SIG04 w0.114: v1(21.34,25.9) 21.42,25.82 21.42,25.11 22.2,24.33 23.02,24.33 23.62,23.73 23.62,23.06 24.73,21.95 25.02,21.95 25.19,21.79 25.19,21.33 26.72,19.79 26.72,6.56 23.41,3.25 22.57,3.25 22.22,2.9 19.7,2.9 19.68,2.92 v1(19.66,2.92) 19.33,3.25 16.38,3.25 16.09,3.55 15.17,3.55 14.61,2.99 9.72,2.99 8.69,4.02 v1(8.51,4.02)
SACT: length 41.9
  TOP w0.076: 18.97,23.45 18.97,23.49 18.95,23.51 18.95,23.8 18.96,23.82 18.96,23.97 18.97,23.98 18.97,23.99 18.88,24.08 18.88,24.37 U1.AC13
  TOP w0.102: UD2.L3 16.11,8.09 v1(16.11,7.83) ; UD1.L3 v1(5.21,8.7) ; 18.97,23.45 19.3,23.12 19.3,22.55 v1(19.17,22.43)
  SIG04 w0.114: v1(5.21,8.7) 5.98,7.93 7.86,7.93 8.21,7.57 9.37,7.57 9.68,7.88 12.23,7.88 12.4,7.71 14.83,7.71 14.95,7.84 16.1,7.84 v1(16.11,7.83) 17.33,7.83 17.9,7.27 20.19,7.27 20.31,7.14 21.16,7.14 22.04,8.02 22.04,9.35 22.44,9.75 22.44,10.86 22.69,11.11 22.69,17.05 22.83,17.19 22.83,18.84 21.9,19.76 21.9,20.53 20.57,21.87 20.03,21.87 19.93,21.97 19.93,22.19 20.03,22.3 20.55,22.3 20.65,22.4 20.65,22.59 20.45,22.79 20,22.79 19.9,22.89 19.9,23.2 19.78,23.32 19.41,23.32 19.29,23.2 19.29,22.55 v1(19.17,22.43)
SBA0: length 42.7
  TOP w0.102: v1(4.3,6.7) UD1.N2 ; v1(19.3,26.43) 19.27,26.46 U1.W13 ; v1(14.3,6.61) 14.3,6.7 UD2.N2
  SIG04 w0.114: v1(4.3,6.7) 7.46,6.7 7.62,6.54 9.85,6.54 10.17,6.86 11.74,6.86 12,6.61 v1(14.3,6.61) 14.35,6.55 17.1,6.55 17.46,6.2 19.26,6.2 19.36,6.1 21.62,6.1 23.14,7.62 23.14,8.96 23.5,9.32 23.5,10.36 23.51,10.36 23.51,10.42 23.77,10.68 23.77,18.99 22.62,20.14 22.62,20.83 21.49,21.95 21.49,22.66 21.47,22.69 19.7,24.45 19.7,24.87 19.67,24.9 19.67,26.07 19.67,26.07 19.67,26.18 19.42,26.43 v1(19.3,26.43)
SBA1: length 40.7
  TOP w0.076: 21.45,23.11 21.45,23.22 20.99,23.68 20.99,23.68 20.38,24.29 20.38,24.66 20.54,24.81 20.54,25.21 U1.AA17
  TOP w0.102: UD1.N8 9.14,6.66 10.56,6.66 v1(10.72,6.5) ; v1(19.1,5.8) 19.1,6.7 UD2.N8 ; 21.45,23.11 21.45,23.1 21.46,23.09 21.46,22.24 22.25,21.45 22.61,21.45 23.97,20.09 24.71,20.09 25.37,19.43 25.37,15.27 25.71,14.93 25.71,11.22 25.18,10.68 25.18,9.02 24.92,8.76 23.68,8.76 v1(23.57,8.87)
  SIG04 w0.114: v1(23.57,8.87) 23.76,8.68 23.76,7.54 23.42,7.21 23.23,7.21 21.77,5.74 19.16,5.74 v1(19.1,5.8) 19.06,5.84 17.31,5.84 16.92,6.23 10.99,6.23 v1(10.72,6.5)
SBG0: length 41.3
  TOP w0.102: v1(4.3,7.5) UD1.M2 ; v1(19.31,25.92) 19.27,25.96 U1.Y13 ; v1(15.12,7.48) 14.7,7.9 UD2.M2
  SIG04 w0.114: v1(4.3,7.5) 4.34,7.54 7.63,7.54 7.95,7.22 9.52,7.22 9.87,7.56 12.04,7.56 12.29,7.32 14.96,7.32 v1(15.12,7.48) 15.13,7.46 17.2,7.46 17.75,6.91 19.64,6.91 19.74,6.81 21.32,6.81 22.39,7.88 22.39,9.2 22.79,9.6 22.79,10.71 23.04,10.96 23.04,16.9 23.05,16.91 23.05,16.95 23.25,17.15 23.25,18.96 22.26,19.95 22.26,20.68 21.18,21.76 21.18,22.53 19.98,23.72 19.49,23.72 19.39,23.83 19.39,25.84 v1(19.31,25.92)
SCAS: length 41.3
  TOP w0.076: U1.AC17 20.93,24.32 20.93,24.18 21.87,23.24 21.87,23.1
  TOP w0.102: UD1.M8 9.07,7.53 9.79,7.53 10.41,8.15 v1(10.41,8.35) ; v1(24.22,9.98) 24.01,10.18 23.72,10.18 23.62,10.08 23.62,9.75 23.52,9.65 23.18,9.65 22.98,9.45 22.98,9.31 23.2,9.1 23.2,8.87 23.09,8.77 22.46,8.77 22.29,8.59 22.29,8.42 22.43,8.29 22.43,8.12 22.31,8 22.14,8 22.04,8.1 21.75,8.1 21.5,7.84 21.5,7.48 21.29,7.27 20.98,7.27 20.73,7.52 v1(20.64,7.52) 20.17,7.52 19.79,7.9 UD2.M8 ; 21.87,23.1 21.87,22.66 22.28,22.25 v1(22.41,22.25)
  SIG04 w0.114: v1(24.22,9.98) 24.47,10.23 24.47,11.01 24.92,11.46 24.92,11.61 24.47,12.05 24.47,12.39 24.62,12.54 24.75,12.54 24.9,12.69 24.9,12.9 24.75,13.05 24.62,13.05 24.47,13.2 24.47,13.41 24.62,13.56 24.75,13.56 24.9,13.71 24.9,13.92 24.75,14.06 24.62,14.06 24.47,14.21 24.47,14.42 24.62,14.57 24.75,14.57 24.9,14.72 24.9,14.93 24.75,15.08 24.62,15.08 24.47,15.23 24.47,15.44 24.62,15.59 24.75,15.59 24.9,15.74 24.9,15.95 24.75,16.1 24.62,16.1 24.47,16.25 24.47,16.46 24.62,16.6 24.75,16.6 24.9,16.75 24.9,16.96 24.75,17.11 24.62,17.11 24.47,17.26 24.47,17.47 24.62,17.62 24.75,17.62 24.9,17.77 24.9,17.98 24.75,18.13 24.62,18.13 24.47,18.28 24.47,18.57 24.56,18.67 24.86,18.67 24.93,18.74 24.93,18.95 24.76,19.12 24.57,19.12 24.47,19.22 24.47,19.37 23.34,20.5 23.34,21.33 v1(22.41,22.25) ; v1(10.41,8.35) 12.27,8.35 12.59,8.03 14.66,8.03 14.86,8.22 17.41,8.22 18,7.63 18.04,7.63 18.05,7.62 20.54,7.62 v1(20.64,7.52)
SCKE0: length 45.7
  TOP w0.076: 21.01,23.12 21.01,23.23 20.07,24.18 20.07,24.82 20.04,24.85 20.04,25.19
  TOP w0.102: U1.AA16 20.29,25.44 20.04,25.19 ; v1(4.3,9.1) UD1.K2 ; UD2.K2 15.1,9.9 15.74,9.9 16.75,10.91 v1(16.75,11.34) 16.78,11.38 17.29,11.38 17.77,10.9 17.77,9.11 18.58,8.3 21.07,8.3 21.21,8.43 21.63,8.43 22.62,9.43 22.62,9.6 25,11.97 25,14.63 24.49,15.14 24.49,18.68 22.37,20.81 22.07,20.81 21.02,21.87 21.02,23.11 21.01,23.12
  SIG04 w0.114: v1(4.3,9.1) 4.3,9.47 5.41,10.57 7.09,10.57 8.06,11.54 8.55,11.54 8.87,11.86 9.39,11.86 9.54,11.72 14.88,11.72 15.12,11.47 16.62,11.47 v1(16.75,11.34)
SCKN: length 39.2
  TOP w0.076: 20.12,23.23 19.5,23.85 19.5,24.14 19.38,24.26 19.38,24.76 19.29,24.86 U1.AB14
  TOP w0.097: 20.12,23.23 20.12,20.95 20.67,20.39 CD42.2 20.62,20.21 20.62,19.93 v1(20.72,19.83) ; UD2.K8 v1(19.1,9.1) ; UD1.K8 v1(8.3,9.1) 7.71,9.1 7.6,9.21 7.12,9.21 6.88,8.97 6.88,3.08 RD6.2
  SIG04 w0.097: v1(8.3,9.1) 8.55,9.34 9.18,9.34 9.82,9.97 12.83,9.97 12.84,9.96 15.5,9.96 15.7,9.76 18.13,9.76 18.55,9.34 18.86,9.34 v1(19.1,9.1) 19.21,9.21 19.49,9.21 19.64,9.35 19.64,9.35 20.44,10.15 20.44,11.41 20.56,11.53 20.96,11.53 21.51,12.08 21.51,16.86 20.66,17.71 20.52,17.85 20.52,19.61 20.72,19.81 v1(20.72,19.83)
SCKP: length 39.2
  TOP w0.076: 19.8,23.23 19.8,23.3 19.32,23.78 19.32,24.07 19.21,24.18 19.21,24.68 19.04,24.85 19.04,25.06 19.29,25.31 U1.AA14
  TOP w0.097: 19.8,23.23 19.8,20.82 19.95,20.67 CD42.1 20.3,20.04 20.3,19.89 v1(20.21,19.8) ; UD2.K7 v1(19.1,9.9) ; v1(8.3,9.9) UD1.K7 7.89,9.48 7.77,9.48 7.73,9.52 6.99,9.52 6.57,9.1 6.57,2.82 RD6.1
  SIG04 w0.097: v1(20.21,19.8) 20.21,17.72 20.29,17.64 21.19,16.73 21.19,12.21 20.83,11.85 20.43,11.85 20.13,11.54 20.13,10.28 19.51,9.67 19.5,9.67 19.36,9.53 19.19,9.53 19.1,9.62 v1(19.1,9.9) 18.86,9.66 18.69,9.66 18.27,10.07 15.84,10.07 15.63,10.28 12.97,10.28 12.96,10.29 9.69,10.29 9.05,9.66 8.55,9.66 v1(8.3,9.9)
SCS0: length 41.6
  TOP w0.076: 19.14,23.71 19.14,24.03 19.05,24.12 19.05,24.62 18.88,24.79 18.79,24.89 U1.AB13
  TOP w0.102: v1(19.38,21.64) 19.38,22.02 19.53,22.17 19.53,23.22 19.14,23.6 19.14,23.71 ; UD1.L7 7.48,8.7 v1(7.34,8.83) ; v1(18.18,10.62) 18.18,9.22 UD2.L7
  SIG04 w0.102: 18.16,10.63 v1(18.18,10.62)
  SIG04 w0.114: v1(7.34,8.83) 7.34,9.8 7.91,10.37 8.98,10.37 9.69,11.08 14.37,11.08 14.66,10.8 15.84,10.8 16.03,10.61 18.14,10.61 18.16,10.63 18.36,10.83 18.36,11.83 18.47,11.94 18.9,11.94 19,11.84 19,11.36 19.23,11.13 19.47,11.13 19.57,11.23 19.57,12 19.49,12.08 19.49,12.58 19.61,12.69 20.3,12.69 20.41,12.8 20.41,15.75 20.31,15.85 20.1,15.85 20.01,15.76 19.54,15.76 19.39,15.9 18.95,15.9 18.78,16.07 18.78,16.69 18.57,16.9 18.36,16.9 18.1,17.15 18.1,17.31 18.4,17.6 19.38,17.6 19.54,17.76 19.54,17.98 19.4,18.11 17.95,18.11 17.82,18.24 17.82,18.5 17.83,18.5 17.94,18.61 19.2,18.61 19.4,18.8 19.4,19.09 19.28,19.21 17.92,19.21 17.82,19.31 17.82,19.49 19.05,20.72 19.05,21.4 19.3,21.64 v1(19.38,21.64)
SDQ0: length 22.1
  TOP w0.102: v1(16.29,25.9) 16.24,25.96 U1.Y7 ; v1(8.3,13.1) UD1.F7
  SIG04 w0.114: v1(16.29,25.9) 15.07,24.68 14.43,24.68 14.33,24.57 14.33,23.94 14.07,23.67 13.48,23.67 13.34,23.53 13.34,22.95 13.04,22.65 12.83,22.65 12.66,22.81 12.45,22.81 12.3,22.66 12.3,22.45 12.47,22.29 12.47,22.08 12.22,21.83 12.22,21.53 12.12,21.43 11.74,21.43 11.63,21.33 11.63,21.03 11.74,20.93 12.13,20.93 12.28,20.78 12.28,20.3 11.81,19.84 10.33,19.84 9.62,19.13 9.62,18.56 9.07,18.01 8.8,18.01 8.69,17.9 8.69,17.73 9.07,17.35 9.07,17.05 8.66,16.64 8.66,16 8.76,15.9 8.87,15.9 8.97,15.8 8.97,15.45 8.87,15.35 8.57,15.35 8.47,15.25 8.47,14.94 8.57,14.84 8.81,14.84 8.91,14.74 8.91,14.36 8.81,14.26 8.65,14.26 8.54,14.16 8.54,13.84 8.3,13.6 v1(8.3,13.1)
SDQ1: length 22.6
  TOP w0.102: v1(7.41,12.02) 7.41,11.77 7.68,11.5 8.3,11.5 UD1.H8 ; v1(16.32,26.93) 16.3,26.96 U1.V7
  SIG04 w0.114: v1(16.32,26.93) 16.67,26.59 16.67,25.72 12.73,21.78 12.73,20.22 11.96,19.46 10.46,19.46 9.99,18.98 9.99,18.02 9.47,17.5 9.47,13.75 9.25,13.53 8.94,13.53 8.73,13.31 8.73,12.94 8.52,12.73 8.12,12.73 v1(7.41,12.02)
SDQ2: length 22.2
  TOP w0.102: v1(15.24,25.95) 15.24,25.96 U1.Y5 ; UD1.J7 7.83,10.3 6.67,11.46 6.67,11.63 v1(6.29,12)
  SIG04 w0.114: v1(15.24,25.95) 14.94,25.65 13.91,25.65 12.97,24.71 12.25,24.71 11.91,24.37 11.91,23.96 11.02,23.07 10.63,23.07 10.01,22.45 10.01,21.82 9.28,21.1 9.28,19.9 7.86,18.48 7.86,16.35 7.76,16.25 7.76,14.1 7.6,13.94 7.6,13.39 7.39,13.18 7.16,13.18 6.91,12.93 6.91,12.16 6.76,12 v1(6.29,12)
SDQ3: length 23.7
  TOP w0.102: UD1.H7 7.54,11.1 7.05,11.58 7.05,12.55 v1(7.28,12.78) ; v1(16.3,26.42) 16.27,26.46 U1.W7
  SIG04 w0.114: v1(7.28,12.78) 7.45,12.78 7.95,13.28 7.95,13.8 8.11,13.96 8.11,16.1 8.27,16.26 8.27,18.35 9.8,19.88 9.8,20.99 10.07,21.26 10.35,21.26 10.56,21.06 10.56,20.45 10.68,20.33 10.99,20.33 11.13,20.46 11.13,22.32 12.05,23.23 12.44,23.23 12.71,23.5 12.71,23.85 13.03,24.17 13.51,24.17 13.83,24.5 13.83,24.97 14.08,25.22 15.05,25.22 16.24,26.42 v1(16.3,26.42)
SDQ4: length 24
  TOP w0.102: UD1.H3 4.3,11.5 2.09,11.5 1.73,11.86 1.73,17.1 9.03,24.39 9.03,25.29 10.2,26.46 U1.W1
SDQ5: length 24.6
  TOP w0.102: v1(14.77,26.52) 14.35,26.52 U1.W4 ; UD1.G2 3.5,12.3 2.19,12.3 2.09,12.4 2.09,16.9 v1(2.36,17.17)
  SIG04 w0.114: v1(2.36,17.17) 2.36,17.73 8.91,24.28 8.91,25.23 9.79,26.11 12.41,26.11 12.82,26.52 v1(14.77,26.52)
SDQ6: length 25.1
  TOP w0.102: U1.W2 13.17,26.46 12.91,26.72 10.17,26.72 8.68,25.22 8.68,24.54 1.38,17.24 1.38,11.44 2.13,10.7 3.5,10.7 UD1.H2
SDQ7: length 27.7
  TOP w0.076: U1.W3 13.54,26.71 13.15,26.71 12.93,26.93
  TOP w0.102: UD1.J3 4.33,9.92 2.4,9.92 1.02,11.3 1.02,17.39 8.35,24.71 8.35,25.18 10.1,26.93 12.93,26.93
SDQ8: length 15.8
  TOP w0.102: UD1.A3 4.48,16.7 4.09,17.09 3.89,17.09 3.78,17.19 3.78,17.41 4.03,17.66 4.18,17.66 4.46,17.37 4.6,17.37 4.7,17.48 4.7,18.33 6.11,19.74 6.11,20.69 6.28,20.86 6.28,21.13 6.5,21.35 6.77,21.35 7,21.58 7,21.85 7.22,22.07 7.49,22.07 7.71,22.29 7.71,22.57 7.94,22.79 8.21,22.79 8.43,23.01 8.43,23.28 8.66,23.51 8.93,23.51 9.15,23.73 9.15,24 9.38,24.23 9.65,24.23 10.14,24.72 11.02,24.72 11.75,25.46 U1.AA1
SDQ9: length 16
  TOP w0.076: 14.14,24.13 14.19,24.18 14.19,24.86 U1.AB4
  TOP w0.102: UD1.C8 8.7,15.03 8.81,14.93 9.05,14.93 9.15,15.03 9.15,15.39 9.3,15.54 10.15,15.54 10.49,15.2 10.63,15.2 10.91,15.48 10.91,15.62 10.51,16.02 10.51,16.19 10.63,16.31 10.8,16.31 11.21,15.9 11.35,15.9 11.88,16.43 11.88,16.97 12.43,17.52 12.43,18.43 12.31,18.55 12.2,18.67 12.2,18.84 12.31,18.96 12.43,19.07 12.43,19.24 12.31,19.36 12.2,19.48 12.2,19.65 12.31,19.77 12.43,19.89 12.43,20.06 12.31,20.17 12.2,20.29 12.2,20.46 12.31,20.58 12.43,20.7 12.43,20.87 12.31,20.99 12.2,21.11 12.2,21.27 12.31,21.39 12.43,21.51 12.43,21.75 13.53,22.85 13.53,23.31 14.14,23.93 14.14,24.13
SDQ10: length 15.6
  TOP w0.102: UD1.C2 3.9,15.01 4.22,14.7 5.02,14.7 5.42,15.09 5.42,18.03 6.83,19.44 6.83,20.4 10.56,24.13 11.34,24.13 12.16,24.96 U1.AB1
SDQ11: length 15.8
  TOP w0.076: 13.45,24.1 13.53,24.18 13.53,24.71 U1.AB3
  TOP w0.102: 13.45,24.1 12.72,23.37 12.72,22.9 12.41,22.59 12.16,22.59 11.75,22.19 11.59,22.19 11.5,22.27 11.33,22.27 11.21,22.16 11.21,21.99 11.3,21.9 11.3,21.73 11.18,21.61 11.01,21.61 10.93,21.7 10.76,21.7 10.64,21.58 10.64,21.41 10.72,21.33 10.72,20.54 9.8,19.61 9.52,19.61 9.21,19.31 9.21,19.17 9.92,18.46 9.92,18.32 9.68,18.09 9.01,18.09 8.37,17.44 7.74,17.44 7.64,17.34 7.64,17.18 7.76,17.06 8.25,17.06 8.35,16.95 8.35,15.76 8.13,15.53 8.01,15.53 7.82,15.35 7.82,15.18 UD1.C7
SDQ12: length 15.5
  TOP w0.102: UD1.B8 8.7,16.22 8.81,16.32 9.05,16.32 9.15,16.42 9.15,16.92 9.25,17.02 9.25,17.16 8.99,17.42 8.99,17.56 9.18,17.75 9.35,17.75 9.47,17.63 9.75,17.63 10.08,17.96 10.34,17.96 10.45,17.86 10.45,17.52 10.33,17.4 10.33,17.17 10.51,17 10.71,17 10.86,17.14 10.86,17.44 11.16,17.74 11.32,17.74 11.48,17.9 11.48,18.11 11.35,18.24 10.55,18.24 10.21,18.58 10.21,19.15 10.55,19.49 10.55,19.8 11.08,20.33 11.08,21.07 12.34,22.33 12.44,22.33 12.99,22.89 12.99,23.35 13.79,24.14 U1.AC3
SDQ13: length 16.3
  TOP w0.076: U1.AA4 14.03,25.21 14.03,24.27 14.02,24.26
  TOP w0.102: UD1.D7 7.9,14.48 8.28,14.86 8.28,15.29 8.49,15.5 8.94,15.5 9.08,15.64 9.08,16 9.37,16.29 10.11,16.29 10.48,16.67 11.01,16.67 11.29,16.39 11.41,16.39 11.58,16.56 11.58,16.71 11.32,16.97 11.32,16.97 11.17,17.11 11.17,17.28 11.29,17.4 11.46,17.4 11.55,17.31 11.72,17.31 11.89,17.48 11.89,17.66 12.1,17.87 12.1,18.07 11.89,18.28 11.89,21.5 13.26,22.87 13.26,23.33 13.97,24.04 13.97,24.21 14.02,24.26
SDQ14: length 16.3
  TOP w0.076: 12.61,24.71 12.89,24.71 13.03,24.85 13.03,25.06 13.18,25.21 13.53,25.21 U1.AA3
  TOP w0.102: 12.61,24.71 12.37,24.71 11.48,23.82 10.75,23.82 7.18,20.25 7.18,19.3 5.77,17.89 5.77,14.88 5.67,14.78 5.63,14.78 5.44,14.59 5.44,14.35 5.34,14.25 4.75,14.25 UD1.D3
SDQ15: length 15.2
  TOP w0.076: U1.AA2 13.14,25.46 12.89,25.21 12.64,25.21
  TOP w0.102: UD1.C3 4.92,15.1 5.06,15.24 5.06,18.18 6.47,19.59 6.47,20.55 10.31,24.39 11.15,24.39 11.96,25.21 12.64,25.21
SDQ16: length 15.3
  TOP w0.102: U1.AC9 16.79,24.25 16.91,24.13 16.91,23.88 16.94,23.85 16.94,21.08 16.67,20.82 16.67,20.6 17.85,19.43 18.02,19.43 18.76,18.68 19.86,18.68 21.47,17.07 21.47,15.26 20.91,14.7 19.37,14.7 19.12,14.45 18.97,14.3 UD2.D7
SDQ17: length 14.3
  TOP w0.076: U1.AB9 16.79,24.86 16.53,24.6 16.53,24.25 16.73,24.05
  TOP w0.102: 16.73,24.05 16.73,21.17 16.36,20.79 16.36,20.49 17.65,19.2 17.75,19.2 18.62,18.33 19.71,18.33 20.11,17.93 20.28,17.93 21.03,17.18 21.03,16.44 21.12,16.35 21.12,15.6 21.02,15.5 20.17,15.5 19.77,15.1 UD2.C8
SDQ18: length 14.5
  TOP w0.076: 15.95,24.22 16.03,24.31 16.03,24.56 16.03,25.06 16.03,25.16
  TOP w0.102: U1.AA8 16.29,25.41 16.03,25.16 ; 15.95,24.22 15.95,24.11 16.12,23.93 16.12,21.76 15.84,21.48 15.84,21.35 15.15,20.66 15.15,19.9 17.33,17.71 17.33,17.23 17.74,16.82 18.18,16.82 18.46,17.1 18.93,17.1 19.15,16.88 19.15,15.73 18.94,15.52 18.48,15.52 18.38,15.41 18.38,15.27 18.55,15.1 UD2.C7
SDQ19: length 14.1
  TOP w0.076: U1.AB8 16.19,24.86 16.19,24.1 16.32,23.96 16.32,23.88
  TOP w0.102: UD2.B8 19.5,16.08 19.87,16.45 19.87,17.16 19.42,17.62 19.25,17.62 19.09,17.46 18.77,17.46 18.61,17.62 18.47,17.62 18.03,17.18 17.89,17.18 17.69,17.37 17.69,17.89 17.78,17.98 17.78,18.15 17.67,18.27 17.5,18.27 17.47,18.25 17.3,18.25 17.19,18.37 17.19,18.54 17.21,18.56 17.21,18.73 17.09,18.85 16.92,18.85 16.9,18.82 16.73,18.82 16.61,18.94 16.61,19.11 16.63,19.13 16.63,19.3 16.52,19.42 16.35,19.42 16.32,19.4 16.15,19.4 16.03,19.52 16.03,19.93 15.89,20.06 15.63,20.06 15.5,20.19 15.5,20.36 15.65,20.5 15.65,20.78 16.32,21.46 16.32,23.88
SDQ20: length 13.5
  TOP w0.102: U1.AC5 14.75,24.42 14.75,23.53 14.38,23.16 14.38,22.66 13.74,22.02 13.74,21.9 13.35,21.5 13.35,19.1 13.71,18.74 13.71,18.57 13.4,18.26 13.4,18.06 13.5,17.95 13.66,17.95 14,18.29 14.17,18.29 14.28,18.17 14.28,18 13.86,17.57 13.86,17.39 13.98,17.27 14.13,17.27 14.57,17.71 14.74,17.71 14.9,17.55 14.9,17.4 14.34,16.84 14.34,16.49 14.5,16.33 15.35,16.33 15.5,16.48 UD2.A3
SDQ21: length 13.9
  TOP w0.076: U1.AB5 14.79,24.81 14.54,24.56 14.54,24.34
  TOP w0.102: 14.54,24.34 14.55,24.32 14.55,23.85 14.55,23.84 14.55,23.7 14.1,23.25 14.1,22.76 13.04,21.71 13.04,17.17 13.04,17.07 12.66,16.68 12.66,16.43 12.76,16.33 14.03,16.33 14.3,16.06 14.3,14.8 14.4,14.7 14.89,14.7 15.29,14.3 UD2.D3
SDQ22: length 16.3
  TOP w0.076: U1.AA6 15.03,25.21 15.03,24.26 14.97,24.2
  TOP w0.102: 14.97,24.2 14.97,23.41 14.67,23.11 14.67,22.64 14.24,22.22 14.24,21.9 13.67,21.33 13.67,19.29 15.85,17.1 15.85,16.11 16.34,15.62 16.34,15.17 16.45,15.07 17.63,15.07 17.78,14.92 17.78,14.78 17.61,14.61 16.19,14.61 15.7,15.1 UD2.C3
SDQ23: length 17
  TOP w0.076: U1.AB6 15.28,24.96 15.19,24.86 15.19,24.15 15.17,24.14
  TOP w0.102: 15.17,24.14 15.17,23.13 15.01,22.97 15.01,22.62 14.57,22.19 14.57,21.73 14.02,21.18 14.02,19.39 16.21,17.21 16.21,16.26 16.7,15.77 16.7,15.64 16.92,15.43 17.48,15.43 17.78,15.43 18.14,15.07 18.14,14.63 17.75,14.25 16.04,14.25 15.6,14.7 15.4,14.7 15,15.1 UD2.C2
SDQ24: length 19.3
  TOP w0.102: v1(16.23,11.85) 16.23,11.03 UD2.J3 ; U1.Y11 18.25,25.96 v1(18.29,25.92)
  SIG04 w0.114: v1(16.23,11.85) 17.12,11.85 17.14,11.87 17.17,11.87 17.68,12.38 17.86,12.57 17.86,13.28 17.98,13.4 17.98,13.64 17.57,14.05 17.57,15.9 16.56,16.92 16.56,19.69 17.23,20.35 17.44,20.57 17.44,20.57 17.99,21.12 17.99,22.23 17.69,22.53 17.69,23.75 18.29,24.35 v1(18.29,25.92)
SDQ25: length 20.1
  TOP w0.102: v1(12.41,13.76) 12.9,13.27 12.9,11.85 13.25,11.5 14.3,11.5 UD2.H2 ; U1.W9 17.27,26.46 17.3,26.42 v1(17.3,26.42)
  SIG04 w0.114: v1(12.41,13.76) 12.41,14.03 11.61,14.83 11.61,18.23 13.15,19.77 13.15,21.57 16.93,25.35 16.93,26.1 17.26,26.42 v1(17.3,26.42)
SDQ26: length 19
  TOP w0.102: v1(15.1,12.3) 15.1,11.5 UD2.H3 ; v1(17.3,26.94) 17.28,26.96 U1.V9
  SIG04 w0.114: v1(17.3,26.94) 17.68,26.57 17.68,24.99 17.58,24.89 17.58,24.73 16.4,23.55 16.4,22.9 13.94,20.44 13.94,19.46 13.64,19.16 13.64,18.18 14.27,17.56 14.27,14.89 14.68,14.48 14.68,12.72 v1(15.1,12.3)
SDQ27: length 18.2
  TOP w0.102: U1.Y9 17.26,25.96 v1(17.31,25.91) ; UD2.G2 14.3,12.3 13.62,12.3 13.45,12.47 13.45,13.3 13.04,13.71 13.04,14.01 12.88,14.17 12.88,14.17 v1(12.61,14.44)
  SIG04 w0.114: v1(12.61,14.44) 12.05,15 12.05,18.16 13.56,19.66 13.56,21.3 17.31,25.05 v1(17.31,25.91)
SDQ28: length 21.2
  TOP w0.102: UD2.H7 19.07,11.47 20.95,11.47 21.62,12.14 23.2,12.14 23.58,12.51 23.58,14.05 21.83,15.79 21.83,17.21 20.01,19.04 18.91,19.04 18.25,19.7 18.07,19.7 17.41,20.36 17.41,20.51 17.73,20.83 17.73,21.05 18.18,21.5 18.18,22.25 17.91,22.52 17.91,24.04 17.79,24.16 U1.AC11
SDQ29: length 18.9
  TOP w0.102: v1(18.3,13.07) 17.92,12.69 17.92,11.92 18.35,11.49 18.35,10.95 18.7,10.6 UD2.J7 ; U1.W11 18.28,26.46 v1(18.3,26.44)
  SIG04 w0.114: v1(18.3,26.44) 18.66,26.07 18.66,24.9 18.64,24.87 18.64,24.15 18.01,23.52 18.01,22.66 18.12,22.55 18.12,22.55 18.31,22.36 18.31,20.99 17.76,20.44 17.36,20.04 17.36,20.04 16.91,19.59 16.91,18.91 16.91,17.09 17.93,16.07 17.93,14.33 18.42,13.84 18.42,13.19 v1(18.3,13.07)
SDQ30: length 21.7
  TOP w0.076: 18.08,24.12 18.08,24.54 17.79,24.83 U1.AB11
  TOP w0.102: 18.08,24.12 18.11,24.08 18.11,22.64 18.39,22.37 18.39,21.42 18.05,21.09 18.05,20.81 17.81,20.57 17.81,20.43 18.31,19.92 18.53,19.92 19.06,19.39 20.15,19.39 22.19,17.36 22.19,15.94 23.93,14.2 23.93,12.37 23.35,11.78 22.03,11.78 20.94,10.7 19.9,10.7 UD2.H8
SDQ31: length 18.9
  TOP w0.102: v1(19.1,13.09) 19.09,13.09 UD2.F7 ; U1.V11 18.29,26.96 v1(18.3,26.95)
  SIG04 w0.114: v1(19.1,13.09) 19.1,13.48 19.41,13.8 19.41,14.11 19.31,14.2 18.64,14.2 18.49,14.35 18.49,14.5 18.59,14.6 19.18,14.6 19.31,14.73 19.31,15.15 19.2,15.25 18.65,15.25 18.25,15.66 18.25,15.94 18.25,15.94 18.25,16.2 18.25,16.2 18.06,16.39 18.06,16.39 17.27,17.18 17.27,19.5 17.49,19.72 17.49,19.72 18.07,20.3 18.62,20.85 18.62,22.5 18.33,22.8 18.33,23.34 18.95,23.96 18.95,24.87 18.93,24.89 18.93,26.32 v1(18.3,26.95)
SDQM0: length 24
  TOP w0.102: v1(16.32,27.44) 16.31,27.46 U1.U7 ; v1(7.24,13.54) 7.86,13.54 UD1.E7
  SIG04 w0.114: v1(7.24,13.54) 6.93,13.85 6.93,15.18 7.31,15.57 7.31,15.97 6.89,16.39 6.89,17.12 6.51,17.5 6.51,18.47 7.47,19.43 8.27,19.43 8.47,19.64 8.47,19.78 8.37,19.88 8.22,19.88 8.12,19.98 8.12,20.28 8.22,20.38 8.67,20.38 8.77,20.49 8.77,20.89 8.67,20.99 8.15,20.99 8.05,21.1 8.05,21.48 8.17,21.6 8.89,21.6 9.07,21.78 9.07,22.17 11.29,24.39 11.29,24.96 11.39,25.07 12.82,25.07 13.06,25.3 13.06,25.79 13.36,26.09 14.87,26.09 16.22,27.44 v1(16.32,27.44)
SDQM1: length 19.8
  TOP w0.076: U1.AA5 14.54,25.21 14.54,24.78 14.36,24.6
  TOP w0.102: UD1.E2 4.3,13.9 8.03,13.9 8.33,14.19 8.33,14.42 8.55,14.65 10.53,14.65 12.22,16.34 12.22,16.78 12.74,17.3 12.74,21.77 13.8,22.83 13.8,23.29 14.36,23.85 14.36,24.6
SDQM2: length 19.8
  TOP w0.076: 16.53,25.17 16.53,24.85 16.36,24.68 16.36,24.15 16.53,23.98
  TOP w0.102: U1.AA9 16.79,25.42 16.53,25.17 ; 16.53,23.98 16.53,21.32 16.02,20.81 16.02,20.42 18.47,17.97 19.56,17.97 19.96,17.57 20.35,17.57 20.67,17.25 20.67,16.54 20.42,16.29 20.12,16.29 19.87,16.04 19.87,15.74 19.63,15.5 19.37,15.5 19.07,15.2 19.07,14.9 18.91,14.74 18.65,14.74 18.35,14.44 18.35,14.34 17.9,13.9 15.89,13.9 15.89,13.9 15.1,13.9 UD2.E2
